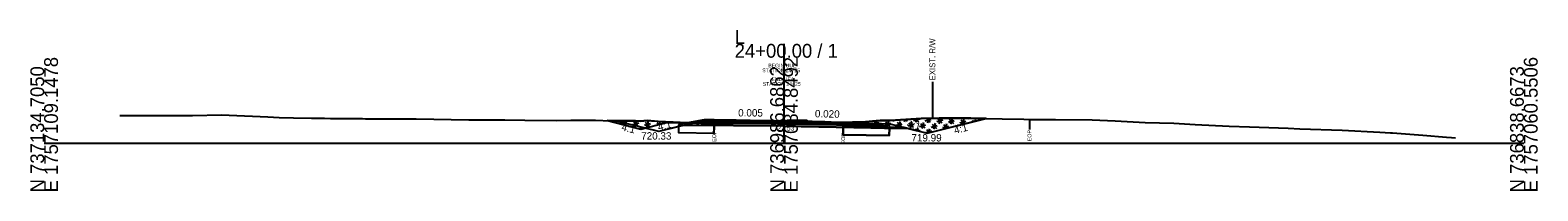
# Model space of a CAD drawing. Extents: x -26 to 4303, y -10 to 9577.
# Drawn here: x 997.2 to 1302.8, y 3990.3 to 4022.9 of the extents above; entities that cross this region are included whole.
import ezdxf

# ---------------------------------------------------------------- set-up
doc = ezdxf.new("R2010")
doc.units = 0
for name, color, linetype in [('Exist CMT Pavement', 7, 'Continuous'), ('Old_Level_2', 7, 'Continuous'), ('Pattern 3', 7, 'Continuous'), ('Prop CMT Conc Surface', 7, 'Continuous'), ('Prop CMT Concrete Structures', 7, 'Continuous'), ('Prop CMT Pvmt Course 1', 7, 'Continuous'), ('Prop CMT Pvmt Course 1 CG', 7, 'Continuous'), ('Prop CMT Pvmt Course 2', 7, 'Continuous'), ('Prop CMT Pvmt Course 2 Wedge', 7, 'Continuous'), ('Prop CMT Pvmt Course 3', 7, 'Continuous'), ('Prop CMT Pvmt Surface', 7, 'Continuous'), ('Prop CMT Pvmt Wedge Surface 1', 7, 'Continuous'), ('Prop CMT Shld Paved Course 1', 7, 'Continuous'), ('Prop CMT Shld Paved Course 2', 7, 'Continuous'), ('Prop CMT Shld Paved Course 3', 7, 'Continuous'), ('Prop CMT Slope Grass', 7, 'Continuous'), ('Prop CMT Subgrade Earthwork', 7, 'Continuous'), ('Prop Road Sect_ Recs - UC Shallow (Outline)', 7, 'Continuous'), ('Prop Shade Light', 7, 'Continuous'), ('Prop XS DDE', 7, 'Continuous'), ('Prop XS DDE Elevations', 7, 'Continuous'), ('Prop XS Ditch Standard Text', 7, 'Continuous'), ('Prop XS Hydro Elevations', 7, 'Continuous'), ('Prop XS SE Text', 7, 'Continuous'), ('Prop XS Side Slope Text', 7, 'Continuous'), ('Scratch_Level_6', 7, 'Continuous')]:
    doc.layers.add(name, color=color, linetype=linetype)

msp = doc.modelspace()

# ---------------------------------------------------------------- linework, layer by layer
at = {"layer": 'Exist CMT Pavement'}
for points in [[(1150, 4004.37), (1136.59, 4004.43)], [(1150, 4004.37), (1150.72, 4004.35)], [(1154.72, 4004.27), (1167.72, 4004.01)]]:
    msp.add_lwpolyline(points, dxfattribs=at)
at = {"layer": 'Old_Level_2'}
for p, q in [((1150, 4000), (1150, 4020.13)), ((1150, 4000), (1150, 4020.13)), ((1000, 4000), (1150, 4000)), ((1000, 4000), (1150, 4000)), ((1150, 4000), (1300, 4000)), ((1150, 4000), (1300, 4000))]:
    msp.add_line(p, q, dxfattribs=at)
at = {"layer": 'Pattern 3'}
for p, q in [((1114.86, 4004.53), (1115.05, 4004.35)), ((1115.32, 4004.53), (1115.26, 4004.29)), ((1117.14, 4004.49), (1118.02, 4003.61)), ((1117.71, 4004.53), (1117.5, 4003.73)), ((1120.1, 4004.52), (1119.78, 4003.33)), ((1120.91, 4004.49), (1120.9, 4004.45)), ((1123.29, 4004.49), (1123.25, 4004.33)), ((1132.24, 4004.3), (1133.44, 4004.62)), ((1132.86, 4004.53), (1132.73, 4004.03)), ((1132.78, 4004.52), (1133.28, 4004.02)), ((1134.59, 4004.18), (1135.8, 4004.5)), ((1134.83, 4004.71), (1135.56, 4003.98)), ((1135.29, 4004.71), (1135.1, 4003.99)), ((1168.23, 4004.46), (1169.11, 4003.57)), ((1168.81, 4004.52), (1168.51, 4003.41)), ((1169.64, 4004.58), (1169.63, 4004.53)), ((1171.19, 4004.5), (1170.87, 4003.29)), ((1172.04, 4004.6), (1171.99, 4004.41)), ((1172.53, 4004.63), (1172.59, 4004.57)), ((1174.47, 4004.75), (1174.34, 4004.29)), ((1174.64, 4004.76), (1174.95, 4004.46)), ((1176.26, 4004.62), (1177.45, 4004.94)), ((1176.89, 4004.9), (1176.7, 4004.18)), ((1176.75, 4004.89), (1177.3, 4004.34)), ((1178.61, 4004.5), (1179.82, 4004.82)), ((1178.89, 4004.99), (1179.66, 4004.22)), ((1179.31, 4005), (1179.06, 4004.06)), ((1180.97, 4004.38), (1182.18, 4004.7)), ((1181.13, 4004.98), (1182.02, 4004.1)), ((1181.71, 4005.07), (1181.41, 4003.94)), ((1182.54, 4005.08), (1182.53, 4005.06)), ((1183.33, 4004.26), (1184.53, 4004.59)), ((1183.49, 4004.87), (1184.37, 4003.98)), ((1184.09, 4005.03), (1183.77, 4003.82)), ((1184.93, 4005.09), (1184.89, 4004.94)), ((1185.68, 4004.14), (1186.89, 4004.47)), ((1185.84, 4004.75), (1186.64, 4003.96)), ((1186.45, 4004.91), (1186.16, 4003.84)), ((1187.31, 4005.06), (1187.24, 4004.82)), ((1187.78, 4005.05), (1187.85, 4004.98)), ((1188.2, 4004.63), (1188.43, 4004.4)), ((1188.8, 4004.79), (1188.72, 4004.48)), ((1189.69, 4005.02), (1189.6, 4004.7)), ((1190.05, 4005.01), (1190.2, 4004.86)), ((1115.48, 4004.24), (1115.83, 4004.33)), ((1116.98, 4003.89), (1118.19, 4004.21)), ((1118.98, 4003.42), (1118.97, 4003.37)), ((1119.33, 4003.77), (1120.54, 4004.09)), ((1119.5, 4004.37), (1120.38, 4003.49)), ((1120.73, 4003.14), (1121.01, 4002.86)), ((1121.34, 4003.3), (1121.23, 4002.92)), ((1121.69, 4003.65), (1122.9, 4003.98)), ((1121.85, 4004.26), (1122.74, 4003.37)), ((1122.46, 4004.42), (1122.13, 4003.21)), ((1124.21, 4004.14), (1124.59, 4003.76)), ((1124.81, 4004.3), (1124.67, 4003.78)), ((1125.64, 4004.34), (1125.61, 4004.21)), ((1127.17, 4004.18), (1127.16, 4004.14)), ((1128, 4004.23), (1127.97, 4004.12)), ((1130.36, 4004.1), (1130.35, 4004.08)), ((1130.89, 4004.18), (1130.92, 4004.14)), ((1136.59, 4004.33), (1136.59, 4004.33)), ((1161.98, 4004.19), (1161.98, 4004.19)), ((1162, 4003.97), (1162.04, 4003.93)), ((1162.4, 4003.58), (1162.51, 4003.46)), ((1163, 4003.74), (1162.93, 4003.45)), ((1163.36, 4004.09), (1163.92, 4004.24)), ((1163.96, 4004.24), (1163.8, 4003.65)), ((1163.97, 4004.24), (1164.4, 4003.81)), ((1164.75, 4003.46), (1164.8, 4003.42)), ((1165.36, 4003.62), (1165.3, 4003.41)), ((1165.71, 4003.97), (1166.92, 4004.3)), ((1166.13, 4004.32), (1166.76, 4003.69)), ((1166.37, 4004.33), (1166.15, 4003.53)), ((1167.71, 4003.5), (1167.68, 4003.36)), ((1168.07, 4003.85), (1169.28, 4004.18)), ((1170.07, 4003.38), (1170.05, 4003.31)), ((1170.42, 4003.74), (1171.63, 4004.06)), ((1170.59, 4004.34), (1171.47, 4003.46)), ((1172.43, 4003.26), (1172.43, 4003.26)), ((1172.78, 4003.62), (1173.99, 4003.94)), ((1172.94, 4004.22), (1173.83, 4003.34)), ((1173.55, 4004.38), (1173.24, 4003.25)), ((1174.78, 4003.14), (1174.77, 4003.1)), ((1175.14, 4003.5), (1176.35, 4003.82)), ((1175.3, 4004.1), (1176.18, 4003.22)), ((1175.9, 4004.26), (1175.58, 4003.06)), ((1176.54, 4002.86), (1176.81, 4002.59)), ((1177.14, 4003.03), (1177.01, 4002.54)), ((1177.23, 4002.49), (1177.58, 4002.58)), ((1177.49, 4003.38), (1178.7, 4003.7)), ((1177.66, 4003.98), (1178.54, 4003.1)), ((1178.26, 4004.15), (1177.94, 4002.94)), ((1178.73, 4002.14), (1179.94, 4002.47)), ((1178.89, 4002.75), (1179.47, 4002.17)), ((1179.5, 4002.91), (1179.29, 4002.12)), ((1179.85, 4003.26), (1181.06, 4003.59)), ((1180.01, 4003.87), (1180.9, 4002.98)), ((1180.62, 4004.03), (1180.29, 4002.82)), ((1181.25, 4002.63), (1181.27, 4002.61)), ((1181.85, 4002.79), (1181.84, 4002.76)), ((1182.21, 4003.14), (1183.41, 4003.47)), ((1182.37, 4003.75), (1183.06, 4003.06)), ((1182.97, 4003.91), (1182.72, 4002.98)), ((1184.73, 4003.63), (1184.85, 4003.51)), ((1185.33, 4003.79), (1185.28, 4003.62))]:
    msp.add_line(p, q, dxfattribs=at)
for points in [[(1121, 4002.86), (1126.19, 4004.15), (1128.64, 4004.11), (1135.88, 4003.97), (1135.87, 4004.71), (1133.8, 4004.7), (1130.46, 4004.1), (1127.54, 4004.25), (1125.97, 4004.32), (1124.51, 4004.4), (1122.99, 4004.51), (1122.33, 4004.56), (1120.84, 4004.48), (1119.9, 4004.53), (1118.33, 4004.53), (1116.48, 4004.53), (1114.88, 4004.53), (1114.21, 4004.56)], [(1179, 4002.05), (1190.81, 4005), (1187.87, 4005.05), (1184.9, 4005.09), (1181.47, 4005.07), (1178.68, 4004.99), (1177.82, 4004.96), (1174.2, 4004.74), (1171.56, 4004.57), (1169.53, 4004.58), (1168.66, 4004.51), (1166.52, 4004.33), (1163.89, 4004.24), (1162.93, 4004.21), (1162.3, 4004.18), (1162, 4004.19), (1162, 4003.47), (1174.28, 4003.23)]]:
    msp.add_lwpolyline(points, close=True, dxfattribs=at)
at = {"layer": 'Prop CMT Conc Surface'}
for p, q in [((1150.72, 4004.23), (1150.72, 4004.73)), ((1150.72, 4004.73), (1154.72, 4004.65)), ((1154.72, 4004.15), (1154.72, 4004.65)), ((1150.72, 4004.23), (1154.72, 4004.15))]:
    msp.add_line(p, q, dxfattribs=at)
for points in [[(1136.59, 4003.97), (1136.59, 4003.97), (1136.59, 4004.18), (1136.59, 4004.18)], [(1136.59, 4004.18), (1136.59, 4003.97)], [(1161.98, 4003.67), (1161.98, 4003.88)], [(1161.98, 4003.88), (1167.72, 4003.76)], [(1167.72, 4003.55), (1161.98, 4003.67)], [(1167.72, 4003.76), (1167.72, 4003.55)]]:
    msp.add_lwpolyline(points, dxfattribs=at)
at = {"layer": 'Prop CMT Concrete Structures'}
for points in [[(1136.59, 4004.18), (1136.59, 4004.43)], [(1150, 4004.24), (1136.59, 4004.31)], [(1136.59, 4004.31), (1136.59, 4004.18), (1136.59, 4004.18)], [(1150, 4004.24), (1161.98, 4004)], [(1161.98, 4004), (1161.98, 4003.88)], [(1161.98, 4003.88), (1167.72, 4003.76)], [(1167.72, 4003.76), (1167.72, 4004.01)]]:
    msp.add_lwpolyline(points, dxfattribs=at)
at = {"layer": 'Prop CMT Pvmt Course 1'}
for points in [[(1136.59, 4003.97), (1136.59, 4003.97), (1136.59, 4003.64), (1136.59, 4003.64)], [(1136.59, 4003.64), (1136.59, 4003.97)], [(1136.59, 4003.97), (1150, 4003.91)], [(1161.98, 4003.67), (1150, 4003.91)], [(1161.98, 4003.67), (1167.72, 4003.55)], [(1161.98, 4003.33), (1161.98, 4003.67)], [(1167.72, 4003.22), (1161.98, 4003.33)], [(1167.72, 4003.55), (1167.72, 4003.22)]]:
    msp.add_lwpolyline(points, dxfattribs=at)
at = {"layer": 'Prop CMT Pvmt Course 2'}
for points in [[(1136.59, 4004.43), (1134.59, 4004.44), (1134.34, 4004.19)], [(1136.59, 4004.18), (1136.59, 4004.43)], [(1134.34, 4004.19), (1136.59, 4004.18)], [(1167.72, 4004.01), (1169.72, 4003.97), (1169.97, 4003.72)], [(1167.72, 4003.76), (1167.72, 4004.01)], [(1169.97, 4003.72), (1167.72, 4003.76)]]:
    msp.add_lwpolyline(points, dxfattribs=at)
at = {"layer": 'Prop CMT Pvmt Course 2 Wedge'}
for points in [[(1134.59, 4004.44), (1132.59, 4004.33), (1124.59, 4002.33), (1115.8, 4004.53)], [(1179, 4001.99), (1191.02, 4005)], [(1169.72, 4003.97), (1171.72, 4003.81), (1179, 4001.99)]]:
    msp.add_lwpolyline(points, dxfattribs=at)
at = {"layer": 'Prop CMT Pvmt Course 3'}
for points in [[(1136.59, 4004.18), (1134.34, 4004.19), (1134.14, 4003.99)], [(1134.14, 4003.99), (1136.59, 4003.97)], [(1136.59, 4003.97), (1136.59, 4004.18)], [(1167.72, 4003.76), (1169.97, 4003.72), (1170.19, 4003.5)], [(1167.72, 4003.55), (1167.72, 4003.76)], [(1170.19, 4003.5), (1167.72, 4003.55)]]:
    msp.add_lwpolyline(points, dxfattribs=at)
at = {"layer": 'Prop CMT Pvmt Surface'}
for points in [[(1136.59, 4004.18), (1136.59, 4004.43)], [(1150, 4004.12), (1136.59, 4004.18)], [(1150, 4004.12), (1167.72, 4003.76)], [(1167.72, 4003.76), (1167.72, 4004.01)]]:
    msp.add_lwpolyline(points, dxfattribs=at)
at = {"layer": 'Prop CMT Pvmt Wedge Surface 1'}
for p, q in [((1149.99, 4003.45), (1129.47, 4003.55)), ((1149.99, 4003.45), (1167.7, 4003.09)), ((1167.7, 4003.09), (1175.18, 4002.95))]:
    msp.add_line(p, q, dxfattribs=at)
at = {"layer": 'Prop CMT Shld Paved Course 1'}
for points in [[(1136.59, 4003.97), (1136.59, 4004.43)], [(1150, 4003.91), (1136.59, 4003.97)], [(1150, 4003.91), (1167.72, 4003.55)], [(1167.72, 4003.55), (1167.72, 4004.01)]]:
    msp.add_lwpolyline(points, dxfattribs=at)
at = {"layer": 'Prop CMT Shld Paved Course 2'}
for points in [[(1136.59, 4004.43), (1134.59, 4004.44)], [(1167.72, 4004.01), (1169.72, 4003.97)]]:
    msp.add_lwpolyline(points, dxfattribs=at)
at = {"layer": 'Prop CMT Shld Paved Course 3'}
for points in [[(1150, 4004.37), (1136.59, 4004.43)], [(1136.59, 4004.43), (1136.59, 4004.18), (1136.59, 4004.18), (1136.59, 4004.31)], [(1136.59, 4004.31), (1150, 4004.24)], [(1136.59, 4004.18), (1150, 4004.12)], [(1150, 4004.37), (1150.72, 4004.35)], [(1161.98, 4004), (1150, 4004.24)], [(1161.98, 4003.88), (1150, 4004.12)], [(1154.72, 4004.27), (1167.72, 4004.01)], [(1161.98, 4003.88), (1161.98, 4004)], [(1167.72, 4003.76), (1161.98, 4003.88)], [(1167.72, 4004.01), (1167.72, 4003.76)]]:
    msp.add_lwpolyline(points, dxfattribs=at)
at = {"layer": 'Prop CMT Slope Grass'}
msp.add_lwpolyline([(1015.36, 4005.58), (1015.68, 4005.59), (1023.59, 4005.6), (1029.61, 4005.58), (1030.08, 4005.57), (1035.96, 4005.71), (1037.53, 4005.66), (1045.38, 4005.31), (1047.64, 4005.22), (1050.52, 4005.16), (1054.17, 4005.08), (1056.86, 4005.04), (1058.02, 4004.96), (1063.42, 4004.99), (1064.51, 4004.96), (1065.17, 4004.94), (1066.63, 4004.94), (1073.95, 4004.93), (1074.87, 4004.93), (1075.43, 4004.92), (1086.11, 4004.69), (1089.07, 4004.73), (1093.38, 4004.72), (1097.43, 4004.66), (1103.82, 4004.6), (1106.75, 4004.63), (1111.76, 4004.64), (1114.85, 4004.53), (1119.87, 4004.53), (1120.82, 4004.48), (1122.35, 4004.56), (1124.24, 4004.42), (1125.89, 4004.33), (1128.3, 4004.22), (1130.51, 4004.1), (1133.78, 4004.7), (1137.25, 4004.71), (1138.24, 4004.72), (1139.88, 4004.69), (1140.31, 4004.69), (1141.35, 4004.68), (1143.13, 4004.67), (1145.38, 4004.61), (1146.98, 4004.58), (1147.91, 4004.56), (1148.6, 4004.55), (1150.11, 4004.53), (1152.09, 4004.46), (1152.98, 4004.43), (1153.51, 4004.43), (1155.69, 4004.4), (1156.79, 4004.35), (1158.29, 4004.3), (1160.94, 4004.21), (1161.42, 4004.19), (1162.21, 4004.18), (1166.53, 4004.33), (1169.52, 4004.58), (1171.55, 4004.57), (1177.8, 4004.96), (1181.8, 4005.08), (1185.53, 4005.09), (1198.6, 4004.86), (1199.76, 4004.82), (1200.94, 4004.82), (1205.05, 4004.8), (1212.47, 4004.7), (1217.12, 4004.55), (1223.24, 4004.21), (1229.04, 4004.02), (1233.34, 4003.76), (1240.27, 4003.44), (1244.4, 4003.31), (1252.22, 4003.01), (1254.6, 4002.93), (1263.16, 4002.6), (1270.77, 4002.2), (1272.98, 4002.08), (1273.35, 4002.06), (1279.54, 4001.64), (1284.3, 4001.2), (1285.32, 4001.15), (1286.13, 4001.08)], dxfattribs=at)
at = {"layer": 'Prop CMT Subgrade Earthwork'}
for points in [[(1136.59, 4003.97), (1134.14, 4003.99), (1133.64, 4003.99), (1133.3, 4003.66)], [(1133.3, 4003.66), (1136.59, 4003.64)], [(1136.59, 4003.64), (1136.59, 4003.97)], [(1167.72, 4003.55), (1170.19, 4003.5), (1170.69, 4003.49), (1171.03, 4003.15)], [(1167.72, 4003.22), (1167.72, 4003.55)], [(1171.03, 4003.15), (1167.72, 4003.22)]]:
    msp.add_lwpolyline(points, dxfattribs=at)
at = {"layer": 'Prop Road Sect_ Recs - UC Shallow (Outline)'}
for points in [[(1129.64, 4003.64), (1128.64, 4003.65), (1128.61, 4002.15), (1135.87, 4002.02), (1135.87, 4003.52)], [(1170.37, 4003.04), (1171.37, 4003.02), (1171.34, 4001.52), (1161.98, 4001.71), (1161.98, 4003.21)]]:
    msp.add_lwpolyline(points, close=True, dxfattribs=at)
at = {"layer": 'Prop Shade Light'}
for p, q in [((1128.64, 4003.65), (1128.61, 4002.15)), ((1128.61, 4002.15), (1135.87, 4002.02)), ((1132.58, 4003.58), (1128.64, 4003.65)), ((1135.87, 4003.52), (1132.58, 4003.58)), ((1135.87, 4002.02), (1135.87, 4003.52)), ((1161.98, 4003.21), (1161.98, 4001.71)), ((1161.98, 4001.71), (1171.34, 4001.52)), ((1171.37, 4003.02), (1171.02, 4003.03)), ((1171.34, 4001.52), (1171.37, 4003.02))]:
    msp.add_line(p, q, dxfattribs=at)
msp.add_lwpolyline([(1171.02, 4003.03), (1167.72, 4003.09), (1161.98, 4003.21)], dxfattribs=at)
at = {"layer": 'Prop XS DDE Elevations'}
for points in [[(1128.3, 4004.22), (1130.51, 4004.1), (1133.78, 4004.7), (1137.25, 4004.71), (1138.24, 4004.72), (1139.88, 4004.69), (1140.31, 4004.69), (1141.35, 4004.68), (1143.13, 4004.67), (1145.38, 4004.61), (1146.98, 4004.58), (1147.91, 4004.56), (1148.6, 4004.55), (1150.11, 4004.53), (1150.72, 4004.51), (1150.72, 4004.35), (1150, 4004.37), (1136.59, 4004.43), (1134.59, 4004.44), (1132.59, 4004.33), (1129.47, 4003.55), (1124.59, 4002.33), (1115.8, 4004.53), (1119.87, 4004.53), (1120.82, 4004.48), (1122.35, 4004.56), (1124.24, 4004.42), (1125.89, 4004.33)], [(1171.72, 4003.81), (1175.18, 4002.95), (1167.7, 4003.09), (1149.99, 4003.45), (1129.47, 4003.55), (1132.59, 4004.33), (1134.59, 4004.44), (1136.59, 4004.43), (1150, 4004.37), (1150.72, 4004.35), (1150.72, 4004.23), (1154.72, 4004.15), (1154.72, 4004.27), (1167.72, 4004.01), (1169.72, 4003.97)], [(1152.98, 4004.43), (1153.51, 4004.43), (1154.72, 4004.41), (1154.72, 4004.27), (1154.72, 4004.15), (1150.72, 4004.23), (1150.72, 4004.35), (1150.72, 4004.51), (1152.09, 4004.46)], [(1171.72, 4003.81), (1175.18, 4002.95), (1179, 4001.99), (1191.02, 4005), (1185.53, 4005.09), (1181.8, 4005.08), (1177.8, 4004.96), (1171.55, 4004.57), (1169.52, 4004.58), (1166.53, 4004.33), (1162.21, 4004.18), (1161.42, 4004.19), (1160.94, 4004.21), (1158.29, 4004.3), (1156.79, 4004.35), (1155.69, 4004.4), (1154.72, 4004.41), (1154.72, 4004.27), (1167.72, 4004.01), (1169.72, 4003.97)]]:
    msp.add_lwpolyline(points, close=True, dxfattribs=at)
at = {"layer": 'Prop XS Ditch Standard Text'}
for p, q in [((1180.08, 4012.43), (1180.08, 4005.03)), ((1135.85, 4004.71), (1135.85, 4002.66)), ((1199.76, 4004.82), (1199.76, 4002.77)), ((1161.98, 4004.19), (1161.98, 4002.14))]:
    msp.add_line(p, q, dxfattribs=at)

# ---------------------------------------------------------------- texts
at = {"layer": 'Old_Level_2'}
for s, p in [('L', (1140, 4020.13)), ('L', (1140, 4020.13)), ('24+00.00 / 1', (1140, 4017.33)), ('24+00.00 / 1', (1140, 4017.33))]:
    msp.add_text(s, height=2.8, dxfattribs=at).set_placement(p)
for s, p in [('E 1757109.1478', (1002.8, 3990)), ('E 1757109.1478', (1002.8, 3990)), ('E 1757084.8492', (1152.8, 3990)), ('E 1757084.8492', (1152.8, 3990)), ('E 1757060.5506', (1302.8, 3990)), ('E 1757060.5506', (1302.8, 3990)), ('N 737134.7050', (1000, 3990)), ('N 737134.7050', (1000, 3990)), ('N 736986.6862', (1150, 3990)), ('N 736986.6862', (1150, 3990)), ('N 736838.6673', (1300, 3990)), ('N 736838.6673', (1300, 3990))]:
    msp.add_text(s, height=2.8, rotation=90, dxfattribs=at).set_placement(p)
at = {"layer": 'Prop CMT Pvmt Course 1 CG'}
msp.add_text('722.53', height=1, dxfattribs=at).set_placement((1147.88, 4002.53))
at = {"layer": 'Prop XS DDE'}
for s, p in [('STATION 24+25', (1145.69, 4011.63)), ('END UEA', (1147.47, 4012.61))]:
    msp.add_text(s, height=0.75, dxfattribs=at).set_placement(p)
at = {"layer": 'Prop XS Ditch Standard Text'}
for s, height, p in [('EXIST. R/W', 1.181, (1180.67, 4012.73)), ('EOP', 0.787, (1136.25, 4000.26)), ('EOP', 0.787, (1162.38, 3999.74)), ('EOP', 0.787, (1200.16, 4000.37))]:
    msp.add_text(s, height=height, rotation=90, dxfattribs=at).set_placement(p)
at = {"layer": 'Prop XS Hydro Elevations'}
for s, p in [('720.33', (1121.04, 4000.71)), ('719.99', (1175.83, 4000.33))]:
    msp.add_text(s, height=1.5, dxfattribs=at).set_placement(p)
at = {"layer": 'Prop XS SE Text'}
for s, rotation, p in [('0.005', 359.7135, (1140.7, 4005.41)), ('0.020', 358.8542, (1156.25, 4005.24))]:
    msp.add_text(s, height=1.5, rotation=rotation, dxfattribs=at).set_placement(p)
at = {"layer": 'Prop XS Side Slope Text'}
for rotation, p in [(14.0362, (1124.6, 4002.49)), (345.9638, (1174.81, 4003.26)), (345.9638, (1116.94, 4002.62)), (14.0362, (1184.66, 4001.84))]:
    msp.add_text('4:1', height=1.5, rotation=rotation, dxfattribs=at).set_placement(p)
at = {"layer": 'Scratch_Level_6'}
for s, p in [('STATION 24+25', (1145.59, 4014.39)), ('BEGIN UUE', (1146.82, 4015.37))]:
    msp.add_text(s, height=0.75, dxfattribs=at).set_placement(p)

doc.saveas('drawing.dxf')
